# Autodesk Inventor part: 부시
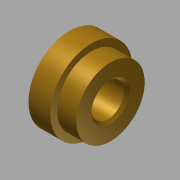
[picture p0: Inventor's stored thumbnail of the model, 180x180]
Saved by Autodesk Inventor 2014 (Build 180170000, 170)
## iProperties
Created: 2011-04
Part Number: 부시
Document SubType Name: Modeling
Designer: 한국산업디자인학원 [http://gmhk.co.kr]
Density: 7.86 g/cm^3
Material: 강철, 연강
Appearance: 황동 - 새틴
Mass: 57.8082 g
Surface Area: 30.152 cm^2
Volume: 7.35473 cm^3
Author: pww
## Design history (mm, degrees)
sketch "스케치1"
  geometry: L1 (0, 0)-(15, 0); L2 (0, 6)-(15, 6); L3 (15, 6)-(15, 12.5); L4 (15, 12.5)-(8, 12.5); L5 (8, 12.5)-(8, 15); L6 (8, 15)-(0, 15); L7 (0, 15)-(0, 6)
  constraints: 14 end point, 4 parallel, 2 vertical alignment, 1 horizontal, 1 perpendicular, 1 vertical
  dimensions: "d0" = 15 distance of L1.start L1.end; "d1" = 12 diameter of L2 L1; "d2" = 25 diameter of L4 L1; "d3" = 8 distance of L5.end L6.end; "d4" = 30 diameter of L6 L1
revolve "회전1" sketch "스케치1" stored, may be unused: angle "d5" = 90 deg
chamfer "모따기1" distance "d6" = 1; stored, may be unused: second distance "d7" = 2, angle "d8" = 45 deg
node "솔리드1"
